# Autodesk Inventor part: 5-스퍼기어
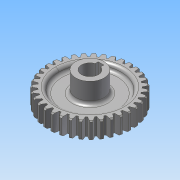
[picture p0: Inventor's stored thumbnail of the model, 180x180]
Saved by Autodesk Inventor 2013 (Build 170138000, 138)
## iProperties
Created: 2013-08
Part Number: 5-스퍼기어
Material: 강
Document SubType Name: Modeling
Designer: 한국산업디자인학원
Categories: <?xml version="1.0" encoding="UTF-16"?> <MemberInstance><Categories><FamilyTemplate><FamilyTemplateParameter ValueType="xs:double" Id="1" ObjectReferenceKey="da
Density: 1 g/cm^3
CustomPartVersion: 1
Author: 한국산업디자인학원
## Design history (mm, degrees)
sketch "Sketch1"
  geometry: C1 r 37 at (0, 0)
  constraints: 1 centre point
  dimensions: "d0" = 74 diameter of C1 (= da_da)
extrude "Extrusion1" new body sketch "Sketch1" distance "d1" = 15 (= da_b); taper "d2" = 0 deg
chamfer "모따기1" distance "d49" = 1; stored, may be unused: second distance "d50" = 2, angle "d51" = 45 deg
workplane "Work Plane2"
feature "피치 지름" dims "d4" = 10, "d5" = 0
workplane "Work Plane8"
workplane "Work Plane9"
feature "스퍼 기어" dims "da_b" = 15, "da_d" = 70, "da_aw" = 70, "da_da" = 74, "da_df" = 65, "da_dw" = 70, angle "da_beta" = 0 deg, "da_lefttooth" = 0, "da_righttooth" = 0
node "작업 평면11"
sketch "스케치6"
  geometry: C1 r 27.5 at (0, 0); A1 r 32.5 centre (0, 0) between (9.347, 31.127) and (7.941, 31.515) reference
  constraints: 1 centre point, 1 coincident
  dimensions: "d63" = 55 diameter of C1
extrude "돌출3" cut sketch "스케치6" distance "d65" = 5; taper "d66" = 0 deg
node "작업 평면12"
sketch "스케치3"
  geometry: C1 r 12.5 at (0, 0); 1 further point
  constraints: 1 centre point, 1 coincident
  dimensions: "d57" = 25 diameter of C1
extrude "돌출2" join sketch "스케치3" distance "d59" = 31; taper "d60" = 0 deg
sketch "스케치7"
  geometry: L1 (2.5, 7.071)-(2.5, 9.8); L2 (2.5, 9.8)-(-2.5, 9.8); L3 (-2.5, 9.8)-(-2.5, 7.071); C1 r 12.5 at (0, 0) reference; A1 r 7.5 centre (0, 0) between (2.5, 7.071) and (-2.5, 7.071)
  constraints: 6 end point, 2 parallel, 2 point on circle, 1 centre point, 1 coincident, 1 perpendicular, 1 vertical
  dimensions: "d68" = 15 diameter of A1; "d70" = 5 distance of L1.end L2.end; "d71" = 17.3 dimension on A1 L2
extrude "돌출4" cut sketch "스케치7" stored distance "d72" = 5; taper "d73" = 0 deg
fillet "모깎기1" dims "d74" = 3
body "Solid1"
mirror "대칭1"
sketch "Sketch2"
  geometry: C1 r 37 at (0, 0) reference; C2 r 35 at (0, 0)
  constraints: 1 centre point, 1 coincident
  dimensions: "d3" = 70 diameter of C2 (= da_dw)
body "Srf1"
other parameters: "d17" = 0, "d34" = 0.8976 (computed from da_z), "d39" = 0, "d41" = 0, "d47" = 0, "d48" = 0, "d52" = 3, "d67" = -7.5
